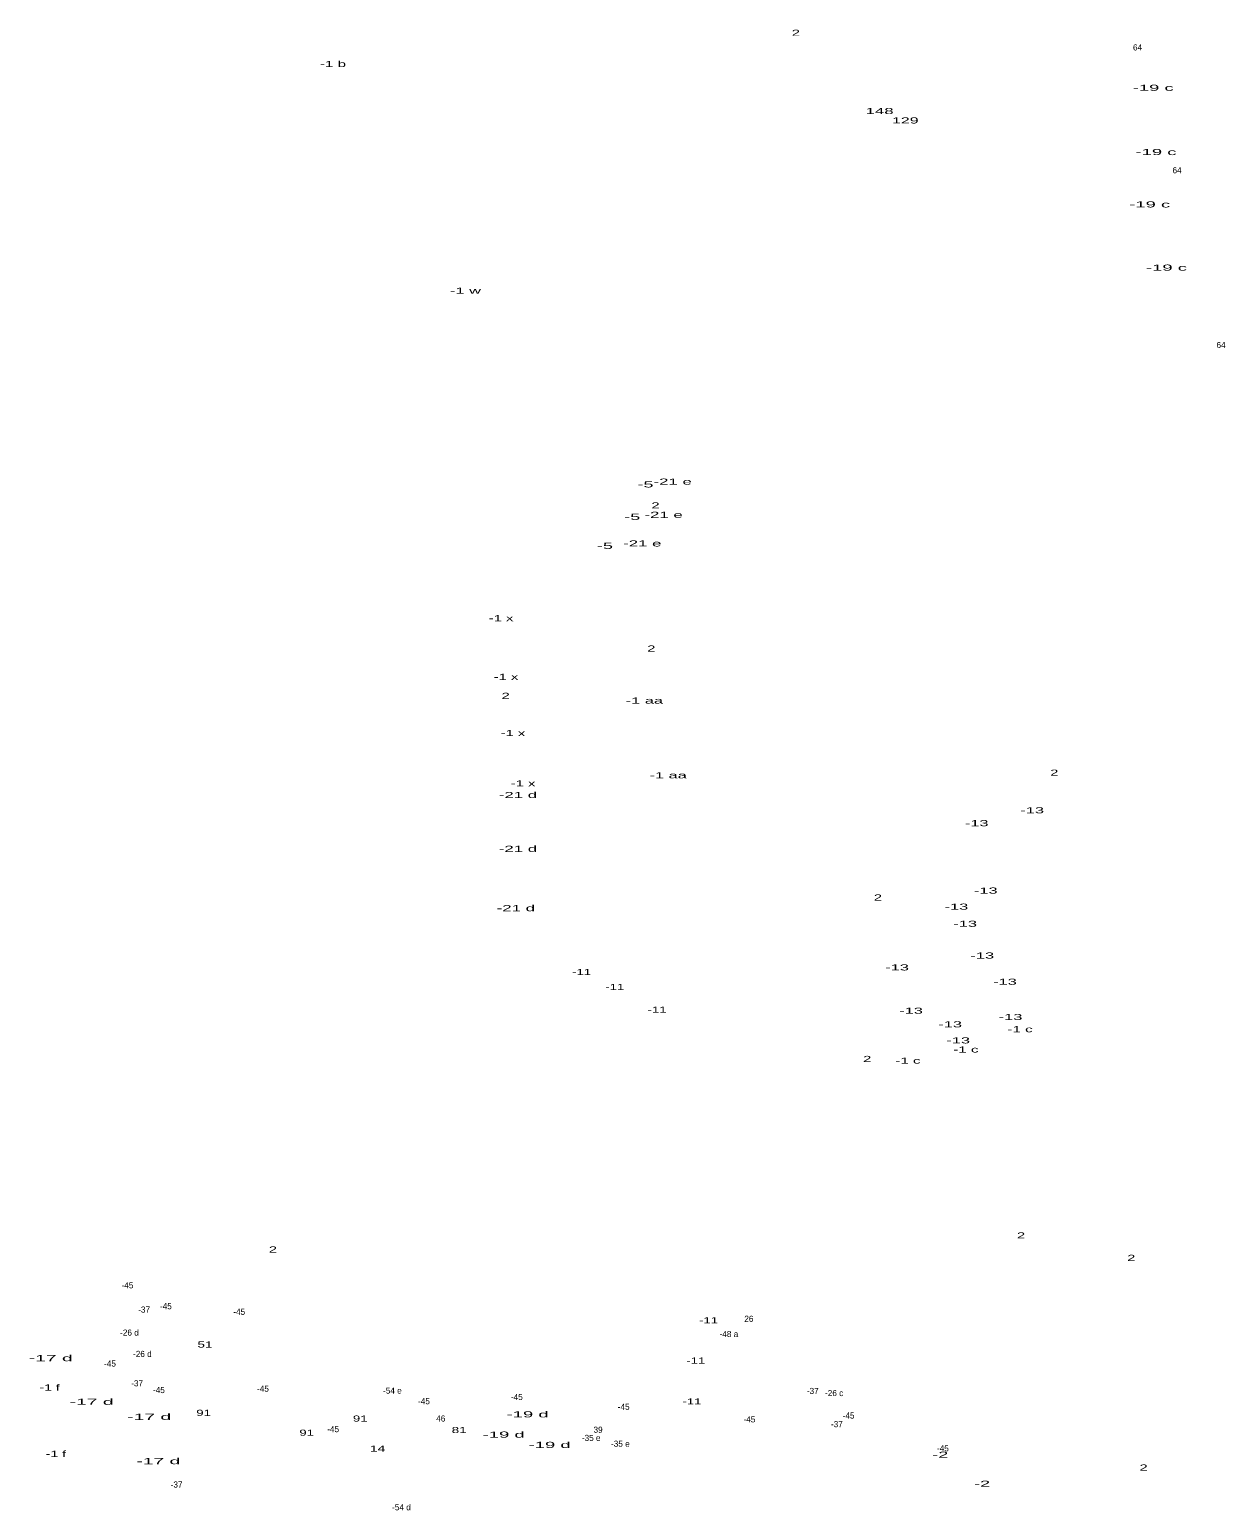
# Model space of a CAD drawing. Extents: x -668622 to -666786, y -990362 to -986505.
# Drawn here: x -668351 to -667571, y -988435 to -987468 of the extents above; entities that cross this region are included whole.
import ezdxf
from ezdxf.enums import TextEntityAlignment as Align

# ---------------------------------------------------------------- set-up
doc = ezdxf.new("R2010")
doc.units = 0
doc.header["$LTSCALE"] = 1.6
doc.layers.add('24', color=7, linetype='Continuous')

msp = doc.modelspace()

# ---------------------------------------------------------------- texts
at = {"layer": '24'}
for s, width, p in [('2', 1.8, (-667851.231, -987471.66)), ('-1 b', 1.85, (-668153.461, -987492.03)), ('-19 c', 2.25, (-667617.979, -987507.57)), ('148', 2.05, (-667796.583, -987522.76)), ('129', 1.95, (-667779.813, -987528.9)), ('-19 c', 2.25, (-667616.159, -987549.53)), ('-19 c', 2.25, (-667620.259, -987583.73)), ('-19 c', 2.25, (-667609.319, -987625.01)), ('-1 w', 2, (-668066.933, -987640.02)), ('-5', 2.2, (-667949.444, -987766.57)), ('-21 e', 2.05, (-667931.701, -987764.75)), ('-21 e', 2.05, (-667937.621, -987786.41)), ('2', 1.8, (-667942.891, -987780.28)), ('-5', 2.2, (-667958.104, -987787.78)), ('-5', 2.2, (-667975.884, -987806.71)), ('-21 e', 2.05, (-667951.531, -987805.11)), ('-1 x', 1.8, (-668043.676, -987853.91)), ('2', 1.8, (-667945.611, -987873.76)), ('-1 x', 1.8, (-668040.486, -987892.22)), ('2', 1.8, (-668040.691, -987904.63)), ('-1 aa', 2, (-667950.147, -987907.72)), ('-1 x', 1.8, (-668035.926, -987928.93)), ('-1 aa', 2, (-667934.637, -987956.52)), ('2', 1.8, (-667682.541, -987954.8)), ('-21 d', 2.05, (-668032.691, -987969.39)), ('-1 x', 1.8, (-668029.316, -987961.77)), ('-13', 2, (-667696.961, -987979.36)), ('-13', 2, (-667733.211, -987987.8)), ('-21 d', 2.05, (-668032.691, -988004.51)), ('2', 1.8, (-667797.641, -988036.29)), ('-13', 2, (-667727.281, -988031.8)), ('-21 d', 2.05, (-668034.061, -988043.27)), ('-13', 2, (-667746.431, -988042.29)), ('-13', 2, (-667740.731, -988053.47)), ('-13', 2, (-667729.561, -988074.22)), ('-11', 1.6, (-667991.117, -988084.93)), ('-13', 2, (-667785.181, -988081.97)), ('-11', 1.6, (-667969.467, -988094.73)), ('-13', 2, (-667714.741, -988091.32)), ('-11', 1.6, (-667941.877, -988109.56)), ('-13', 2, (-667776.071, -988110.25)), ('-13', 2, (-667711.091, -988114.35)), ('-13', 2, (-667750.531, -988119.14)), ('-1 c', 1.85, (-667704.905, -988122.33)), ('-13', 2, (-667745.291, -988129.63)), ('-1 c', 1.85, (-667740.245, -988135.56)), ('2', 1.8, (-667804.711, -988141.75)), ('-1 c', 1.85, (-667778.085, -988142.85)), ('2', 1.8, (-667704.251, -988256.95)), ('2', 1.8, (-668192.611, -988266.14)), ('2', 1.8, (-667632.261, -988271.63)), ('-11', 1.6, (-667908.267, -988312.37)), ('51', 1.65, (-668237.017, -988328.22)), ('-17 d', 2.35, (-668337.725, -988337.1)), ('-11', 1.6, (-667916.587, -988338.7)), ('-1 f', 1.7, (-668338.473, -988356.26)), ('-17 d', 2.35, (-668311.045, -988365.61)), ('-11', 1.6, (-667919.097, -988365.39)), ('-17 d', 2.35, (-668273.425, -988375.41)), ('91', 1.6, (-668237.913, -988372.82)), ('91', 1.6, (-668135.663, -988376.57)), ('-19 d', 2.25, (-668026.395, -988373.82)), ('91', 1.6, (-668170.643, -988385.79)), ('81', 1.65, (-668071.077, -988384.05)), ('-19 d', 2.25, (-668042.005, -988387.04)), ('14', 1.7, (-668124.353, -988396.2)), ('-19 d', 2.25, (-668012.025, -988393.77)), ('-1 f', 1.7, (-668334.363, -988399.58)), ('-17 d', 2.35, (-668267.505, -988404.37)), ('-2', 2.2, (-667756.994, -988400.16)), ('2', 1.8, (-667624.211, -988408.57)), ('-2', 2.2, (-667729.684, -988419.12))]:
    msp.add_text(s, height=4, dxfattribs=dict(at, width=width)).set_placement(p, align=Align.CENTER)
for s, p in [('64', (-667628.187, -987481.23)), ('64', (-667602.367, -987561.44)), ('64', (-667573.667, -987675.55)), ('-45', (-668287.609, -988289.54)), ('-37', (-668276.751, -988305.4)), ('-45', (-668262.539, -988303.22)), ('-45', (-668214.659, -988306.87)), ('26', (-667881.923, -988311.43)), ('-26 d', (-668286.314, -988320.45)), ('-48 a', (-667894.977, -988321.37)), ('-26 d', (-668277.884, -988334.36)), ('-45', (-668299.009, -988340.62)), ('-37', (-668281.311, -988353.52)), ('-45', (-668267.099, -988357.95)), ('-45', (-668199.159, -988357.04)), ('-54 e', (-668114.672, -988358.31)), ('-45', (-668094.059, -988365.24)), ('-45', (-668033.419, -988362.51)), ('-37', (-667840.221, -988358.54)), ('-26 c', (-667826.254, -988359.91)), ('46', (-668083.087, -988376.53)), ('-45', (-667963.659, -988368.89)), ('-45', (-667881.579, -988377.1)), ('-45', (-667816.839, -988374.59)), ('-45', (-668153.329, -988383.48)), ('39', (-667980.383, -988383.87)), ('-37', (-667824.491, -988380.21)), ('-35 e', (-667984.873, -988389.21)), ('-35 e', (-667965.833, -988392.97)), ('-45', (-667755.289, -988396.03)), ('-37', (-668255.551, -988419.65)), ('-54 d', (-668108.752, -988434.48))]:
    msp.add_text(s, height=4, dxfattribs=at).set_placement(p, align=Align.CENTER)

doc.saveas('drawing.dxf')
